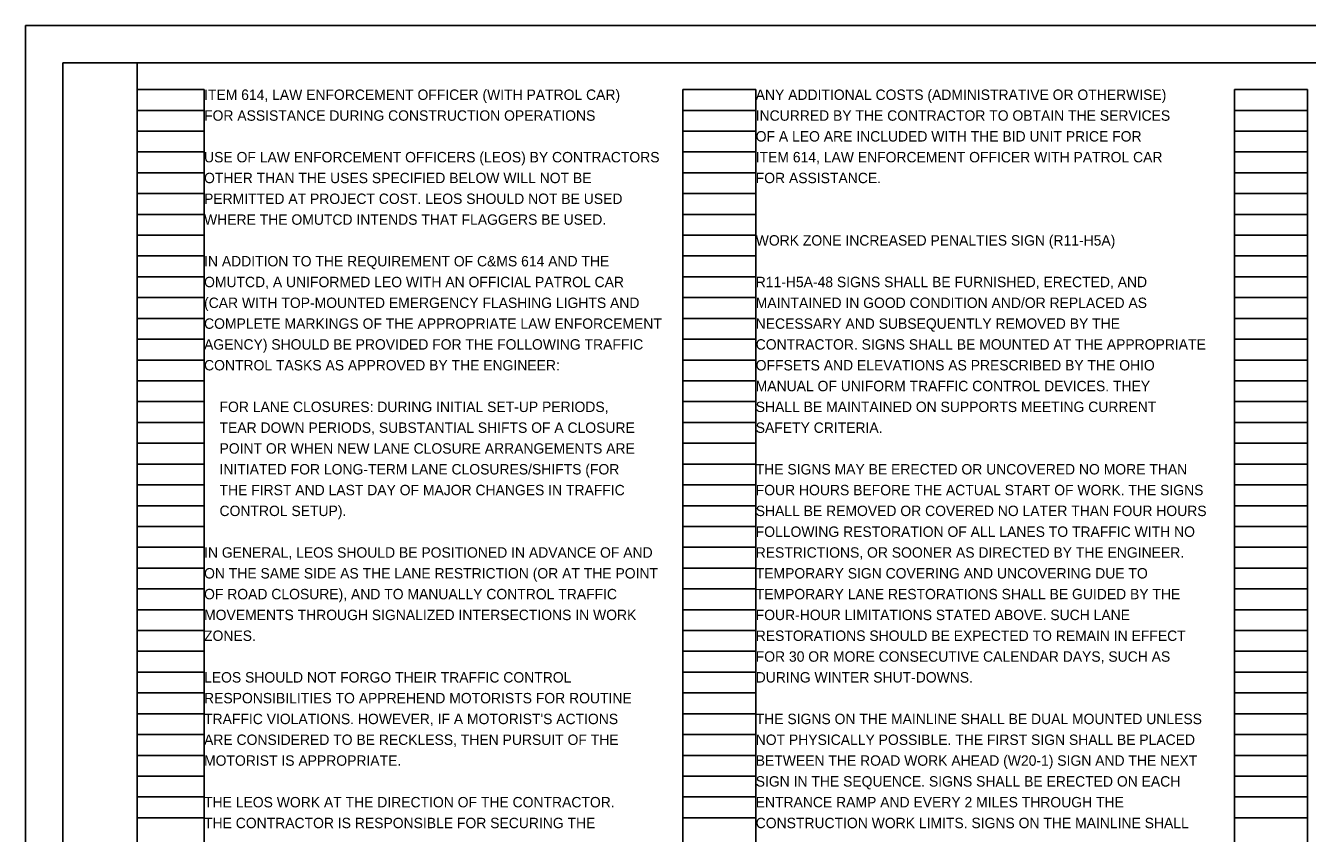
# Model space of a CAD drawing. Extents: x 0 to 34, y 0 to 22.
# Drawn here: x 0 to 17.24, y 11.13 to 22 of the extents above; entities that cross this region are included whole.
import ezdxf

# ---------------------------------------------------------------- set-up
doc = ezdxf.new("R2010")
doc.units = 0
for name, color, linetype in [('SH_Border', 7, 'Continuous'), ('SH_Cut_Line', 7, 'Continuous'), ('SH_Data', 7, 'Continuous'), ('SH_Text', 7, 'Continuous')]:
    doc.layers.add(name, color=color, linetype=linetype)

msp = doc.modelspace()

# ---------------------------------------------------------------- linework, layer by layer
at = {"layer": 'SH_Border'}
for points in [[(0.5, 21.5), (1.5, 21.5), (1.5, 0.5), (0.5, 0.5)], [(1.5, 21.5), (33.5, 21.5), (33.5, 0.5), (1.5, 0.5)]]:
    msp.add_lwpolyline(points, close=True, dxfattribs=at)
at = {"layer": 'SH_Cut_Line'}
msp.add_lwpolyline([(0, 0), (34, 0), (34, 22), (0, 22)], close=True, dxfattribs=at)
at = {"layer": 'SH_Data'}
for p, q in [((1.5, 0.98), (1.5, 21.14)), ((1.5, 21.14), (2.4, 21.14)), ((2.4, 0.98), (2.4, 21.14)), ((8.84, 0.98), (8.84, 21.14)), ((8.84, 21.14), (9.82, 21.14)), ((9.82, 0.98), (9.82, 21.14)), ((16.26, 0.98), (16.26, 21.14)), ((16.26, 21.14), (17.24, 21.14)), ((17.24, 0.98), (17.24, 21.14)), ((1.5, 20.86), (2.4, 20.86)), ((8.84, 20.86), (9.82, 20.86)), ((16.26, 20.86), (17.24, 20.86)), ((1.5, 20.58), (2.4, 20.58)), ((8.84, 20.58), (9.82, 20.58)), ((16.26, 20.58), (17.24, 20.58)), ((1.5, 20.3), (2.4, 20.3)), ((8.84, 20.3), (9.82, 20.3)), ((16.26, 20.3), (17.24, 20.3)), ((1.5, 20.02), (2.4, 20.02)), ((8.84, 20.02), (9.82, 20.02)), ((16.26, 20.02), (17.24, 20.02)), ((1.5, 19.74), (2.4, 19.74)), ((8.84, 19.74), (9.82, 19.74)), ((16.26, 19.74), (17.24, 19.74)), ((1.5, 19.46), (2.4, 19.46)), ((8.84, 19.46), (9.82, 19.46)), ((16.26, 19.46), (17.24, 19.46)), ((1.5, 19.18), (2.4, 19.18)), ((8.84, 19.18), (9.82, 19.18)), ((16.26, 19.18), (17.24, 19.18)), ((1.5, 18.9), (2.4, 18.9)), ((8.84, 18.9), (9.82, 18.9)), ((16.26, 18.9), (17.24, 18.9)), ((1.5, 18.62), (2.4, 18.62)), ((8.84, 18.62), (9.82, 18.62)), ((16.26, 18.62), (17.24, 18.62)), ((1.5, 18.34), (2.4, 18.34)), ((8.84, 18.34), (9.82, 18.34)), ((16.26, 18.34), (17.24, 18.34)), ((1.5, 18.06), (2.4, 18.06)), ((8.84, 18.06), (9.82, 18.06)), ((16.26, 18.06), (17.24, 18.06)), ((1.5, 17.78), (2.4, 17.78)), ((8.84, 17.78), (9.82, 17.78)), ((16.26, 17.78), (17.24, 17.78)), ((1.5, 17.5), (2.4, 17.5)), ((8.84, 17.5), (9.82, 17.5)), ((16.26, 17.5), (17.24, 17.5)), ((1.5, 17.22), (2.4, 17.22)), ((8.84, 17.22), (9.82, 17.22)), ((16.26, 17.22), (17.24, 17.22)), ((1.5, 16.94), (2.4, 16.94)), ((8.84, 16.94), (9.82, 16.94)), ((16.26, 16.94), (17.24, 16.94)), ((1.5, 16.66), (2.4, 16.66)), ((8.84, 16.66), (9.82, 16.66)), ((16.26, 16.66), (17.24, 16.66)), ((1.5, 16.38), (2.4, 16.38)), ((8.84, 16.38), (9.82, 16.38)), ((16.26, 16.38), (17.24, 16.38)), ((1.5, 16.1), (2.4, 16.1)), ((8.84, 16.1), (9.82, 16.1)), ((16.26, 16.1), (17.24, 16.1)), ((1.5, 15.82), (2.4, 15.82)), ((8.84, 15.82), (9.82, 15.82)), ((16.26, 15.82), (17.24, 15.82)), ((1.5, 15.54), (2.4, 15.54)), ((8.84, 15.54), (9.82, 15.54)), ((16.26, 15.54), (17.24, 15.54)), ((1.5, 15.26), (2.4, 15.26)), ((8.84, 15.26), (9.82, 15.26)), ((16.26, 15.26), (17.24, 15.26)), ((1.5, 14.98), (2.4, 14.98)), ((8.84, 14.98), (9.82, 14.98)), ((16.26, 14.98), (17.24, 14.98)), ((1.5, 14.7), (2.4, 14.7)), ((8.84, 14.7), (9.82, 14.7)), ((16.26, 14.7), (17.24, 14.7)), ((1.5, 14.42), (2.4, 14.42)), ((8.84, 14.42), (9.82, 14.42)), ((16.26, 14.42), (17.24, 14.42)), ((1.5, 14.14), (2.4, 14.14)), ((8.84, 14.14), (9.82, 14.14)), ((16.26, 14.14), (17.24, 14.14)), ((1.5, 13.86), (2.4, 13.86)), ((8.84, 13.86), (9.82, 13.86)), ((16.26, 13.86), (17.24, 13.86)), ((1.5, 13.58), (2.4, 13.58)), ((8.84, 13.58), (9.82, 13.58)), ((16.26, 13.58), (17.24, 13.58)), ((1.5, 13.3), (2.4, 13.3)), ((8.84, 13.3), (9.82, 13.3)), ((16.26, 13.3), (17.24, 13.3)), ((1.5, 13.02), (2.4, 13.02)), ((8.84, 13.02), (9.82, 13.02)), ((16.26, 13.02), (17.24, 13.02)), ((1.5, 12.74), (2.4, 12.74)), ((8.84, 12.74), (9.82, 12.74)), ((16.26, 12.74), (17.24, 12.74)), ((1.5, 12.46), (2.4, 12.46)), ((8.84, 12.46), (9.82, 12.46)), ((16.26, 12.46), (17.24, 12.46)), ((1.5, 12.18), (2.4, 12.18)), ((8.84, 12.18), (9.82, 12.18)), ((16.26, 12.18), (17.24, 12.18)), ((1.5, 11.9), (2.4, 11.9)), ((8.84, 11.9), (9.82, 11.9)), ((16.26, 11.9), (17.24, 11.9)), ((1.5, 11.62), (2.4, 11.62)), ((8.84, 11.62), (9.82, 11.62)), ((16.26, 11.62), (17.24, 11.62)), ((1.5, 11.34), (2.4, 11.34)), ((8.84, 11.34), (9.82, 11.34)), ((16.26, 11.34), (17.24, 11.34))]:
    msp.add_line(p, q, dxfattribs=at)

# ---------------------------------------------------------------- texts
at = {"layer": 'SH_Text'}
for s, p in [('ITEM 614, LAW ENFORCEMENT OFFICER (WITH PATROL CAR)', (2.4, 21)), ('ANY ADDITIONAL COSTS (ADMINISTRATIVE OR OTHERWISE)', (9.82, 21)), ('FOR ASSISTANCE DURING CONSTRUCTION OPERATIONS', (2.4, 20.72)), ('INCURRED BY THE CONTRACTOR TO OBTAIN THE SERVICES', (9.82, 20.72)), ('OF A LEO ARE INCLUDED WITH THE BID UNIT PRICE FOR', (9.82, 20.44)), ('USE OF LAW ENFORCEMENT OFFICERS (LEOS) BY CONTRACTORS', (2.4, 20.16)), ('ITEM 614, LAW ENFORCEMENT OFFICER WITH PATROL CAR', (9.82, 20.16)), ('OTHER THAN THE USES SPECIFIED BELOW WILL NOT BE', (2.4, 19.88)), ('FOR ASSISTANCE.', (9.82, 19.88)), ('PERMITTED AT PROJECT COST. LEOS SHOULD NOT BE USED', (2.4, 19.6)), ('WHERE THE OMUTCD INTENDS THAT FLAGGERS BE USED.', (2.4, 19.32)), ('WORK ZONE INCREASED PENALTIES SIGN (R11-H5A)', (9.82, 19.04)), ('IN ADDITION TO THE REQUIREMENT OF C&MS 614 AND THE', (2.4, 18.76)), ('OMUTCD, A UNIFORMED LEO WITH AN OFFICIAL PATROL CAR', (2.4, 18.48)), ('R11-H5A-48 SIGNS SHALL BE FURNISHED, ERECTED, AND', (9.82, 18.48)), ('(CAR WITH TOP-MOUNTED EMERGENCY FLASHING LIGHTS AND', (2.4, 18.2)), ('MAINTAINED IN GOOD CONDITION AND/OR REPLACED AS', (9.82, 18.2)), ('COMPLETE MARKINGS OF THE APPROPRIATE LAW ENFORCEMENT', (2.4, 17.92)), ('NECESSARY AND SUBSEQUENTLY REMOVED BY THE', (9.82, 17.92)), ('AGENCY) SHOULD BE PROVIDED FOR THE FOLLOWING TRAFFIC', (2.4, 17.64)), ('CONTRACTOR. SIGNS SHALL BE MOUNTED AT THE APPROPRIATE', (9.82, 17.64)), ('CONTROL TASKS AS APPROVED BY THE ENGINEER:', (2.4, 17.36)), ('OFFSETS AND ELEVATIONS AS PRESCRIBED BY THE OHIO', (9.82, 17.36)), ('MANUAL OF UNIFORM TRAFFIC CONTROL DEVICES. THEY', (9.82, 17.08)), ('    FOR LANE CLOSURES: DURING INITIAL SET-UP PERIODS,', (2.4, 16.8)), ('SHALL BE MAINTAINED ON SUPPORTS MEETING CURRENT', (9.82, 16.8)), ('    TEAR DOWN PERIODS, SUBSTANTIAL SHIFTS OF A CLOSURE', (2.4, 16.52)), ('SAFETY CRITERIA.', (9.82, 16.52)), ('    POINT OR WHEN NEW LANE CLOSURE ARRANGEMENTS ARE', (2.4, 16.24)), ('    INITIATED FOR LONG-TERM LANE CLOSURES/SHIFTS (FOR', (2.4, 15.96)), ('THE SIGNS MAY BE ERECTED OR UNCOVERED NO MORE THAN', (9.82, 15.96)), ('    THE FIRST AND LAST DAY OF MAJOR CHANGES IN TRAFFIC', (2.4, 15.68)), ('FOUR HOURS BEFORE THE ACTUAL START OF WORK. THE SIGNS', (9.82, 15.68)), ('    CONTROL SETUP).', (2.4, 15.4)), ('SHALL BE REMOVED OR COVERED NO LATER THAN FOUR HOURS', (9.82, 15.4)), ('FOLLOWING RESTORATION OF ALL LANES TO TRAFFIC WITH NO', (9.82, 15.12)), ('IN GENERAL, LEOS SHOULD BE POSITIONED IN ADVANCE OF AND', (2.4, 14.84)), ('RESTRICTIONS, OR SOONER AS DIRECTED BY THE ENGINEER.', (9.82, 14.84)), ('ON THE SAME SIDE AS THE LANE RESTRICTION (OR AT THE POINT', (2.4, 14.56)), ('TEMPORARY SIGN COVERING AND UNCOVERING DUE TO', (9.82, 14.56)), ('OF ROAD CLOSURE), AND TO MANUALLY CONTROL TRAFFIC', (2.4, 14.28)), ('TEMPORARY LANE RESTORATIONS SHALL BE GUIDED BY THE', (9.82, 14.28)), ('MOVEMENTS THROUGH SIGNALIZED INTERSECTIONS IN WORK', (2.4, 14)), ('FOUR-HOUR LIMITATIONS STATED ABOVE. SUCH LANE', (9.82, 14)), ('ZONES.', (2.4, 13.72)), ('RESTORATIONS SHOULD BE EXPECTED TO REMAIN IN EFFECT', (9.82, 13.72)), ('FOR 30 OR MORE CONSECUTIVE CALENDAR DAYS, SUCH AS', (9.82, 13.44)), ('LEOS SHOULD NOT FORGO THEIR TRAFFIC CONTROL', (2.4, 13.16)), ('DURING WINTER SHUT-DOWNS.', (9.82, 13.16)), ('RESPONSIBILITIES TO APPREHEND MOTORISTS FOR ROUTINE', (2.4, 12.88)), ("TRAFFIC VIOLATIONS. HOWEVER, IF A MOTORIST'S ACTIONS", (2.4, 12.6)), ('THE SIGNS ON THE MAINLINE SHALL BE DUAL MOUNTED UNLESS', (9.82, 12.6)), ('ARE CONSIDERED TO BE RECKLESS, THEN PURSUIT OF THE', (2.4, 12.32)), ('NOT PHYSICALLY POSSIBLE. THE FIRST SIGN SHALL BE PLACED', (9.82, 12.32)), ('MOTORIST IS APPROPRIATE.', (2.4, 12.04)), ('BETWEEN THE ROAD WORK AHEAD (W20-1) SIGN AND THE NEXT', (9.82, 12.04)), ('SIGN IN THE SEQUENCE. SIGNS SHALL BE ERECTED ON EACH', (9.82, 11.76)), ('THE LEOS WORK AT THE DIRECTION OF THE CONTRACTOR.', (2.4, 11.48)), ('ENTRANCE RAMP AND EVERY 2 MILES THROUGH THE', (9.82, 11.48)), ('THE CONTRACTOR IS RESPONSIBLE FOR SECURING THE', (2.4, 11.2)), ('CONSTRUCTION WORK LIMITS. SIGNS ON THE MAINLINE SHALL', (9.82, 11.2))]:
    msp.add_text(s, height=0.14, dxfattribs=at).set_placement(p)

doc.saveas('drawing.dxf')
